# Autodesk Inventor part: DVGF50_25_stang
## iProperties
Created: 2010-04
Part Number: DVGF50_25_stang
Document SubType Name: Modeling
Designer: TB
Mass: 191.687 g
Surface Area: 286.032 cm^2
Volume: 191.687 cm^3
Density: 1 g/cm^3
Author: TB
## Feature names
1. Revolution1
2. Fillet1
3. Revolution2
4. Extrusion1
5. Extrusion2
6. Chamfer1
7. Chamfer2
